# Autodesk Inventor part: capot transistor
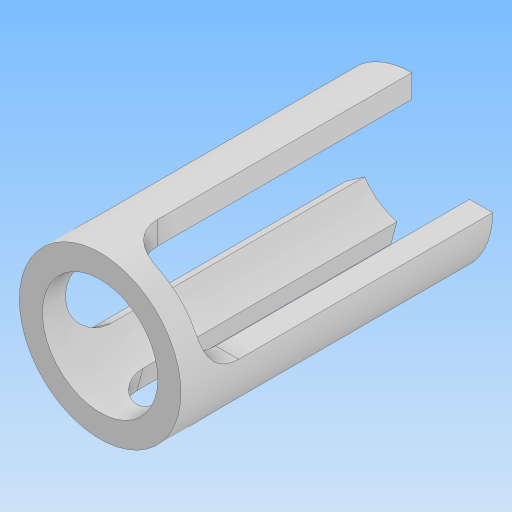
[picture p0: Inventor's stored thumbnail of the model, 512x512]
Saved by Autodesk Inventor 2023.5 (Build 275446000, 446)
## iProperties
Created: 2025-09
Part Number: capot transistor
Material: Générique
Document SubType Name: Modeling
Designer: admin
Density: 1 g/cm^3
Appearance: Par défaut
Author: admin
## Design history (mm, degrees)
sketch "Esquisse1"
  geometry: C1 r 5 at (0, 0); C2 r 7 at (0, 0); 1 further point
  constraints: 2 centre point, 2 coincident
  dimensions: "d0" = 10 diameter of C1; "d1" = 14 diameter of C2
extrude "Extrusion1" new body sketch "Esquisse1" distance "d2" = 2; taper "d3" = 0 deg
sketch "Esquisse2"
  geometry: L1 (0, 0)-(0, 7); L2 (0, 0)-(4.5, 5.362); L3 (0, 0)-(-5.362, -4.5); L4 (0, 0)-(-7, 0); L5 (0, 0)-(5.734, -4.015); L6 (0, 0)-(1.812, -6.761); C1 r 7 at (0, 0) reference; C2 r 5 at (0, 0) reference; C3 r 5 at (0, 0) reference; A1 r 7 centre (0, 0) between (0, 7) and (4.5, 5.362) reference; 13 further points
  constraints: 12 end point, 6 point on circle, 1 horizontal, 1 vertical
  dimensions: "d4" = 40 deg angle of L1 L2; "d5" = 40 deg angle of L3 L4; "d6" = 65 deg angle of L6 L3; "d8" = 40 deg angle of L6 L5
extrude "Extrusion2" join sketch "Esquisse2" distance "d9" = 25; taper "d10" = 0 deg
fillet "Congé1" dims "d11" = 3
node "Solide1"
